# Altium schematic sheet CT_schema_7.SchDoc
size 371 x 336 mm
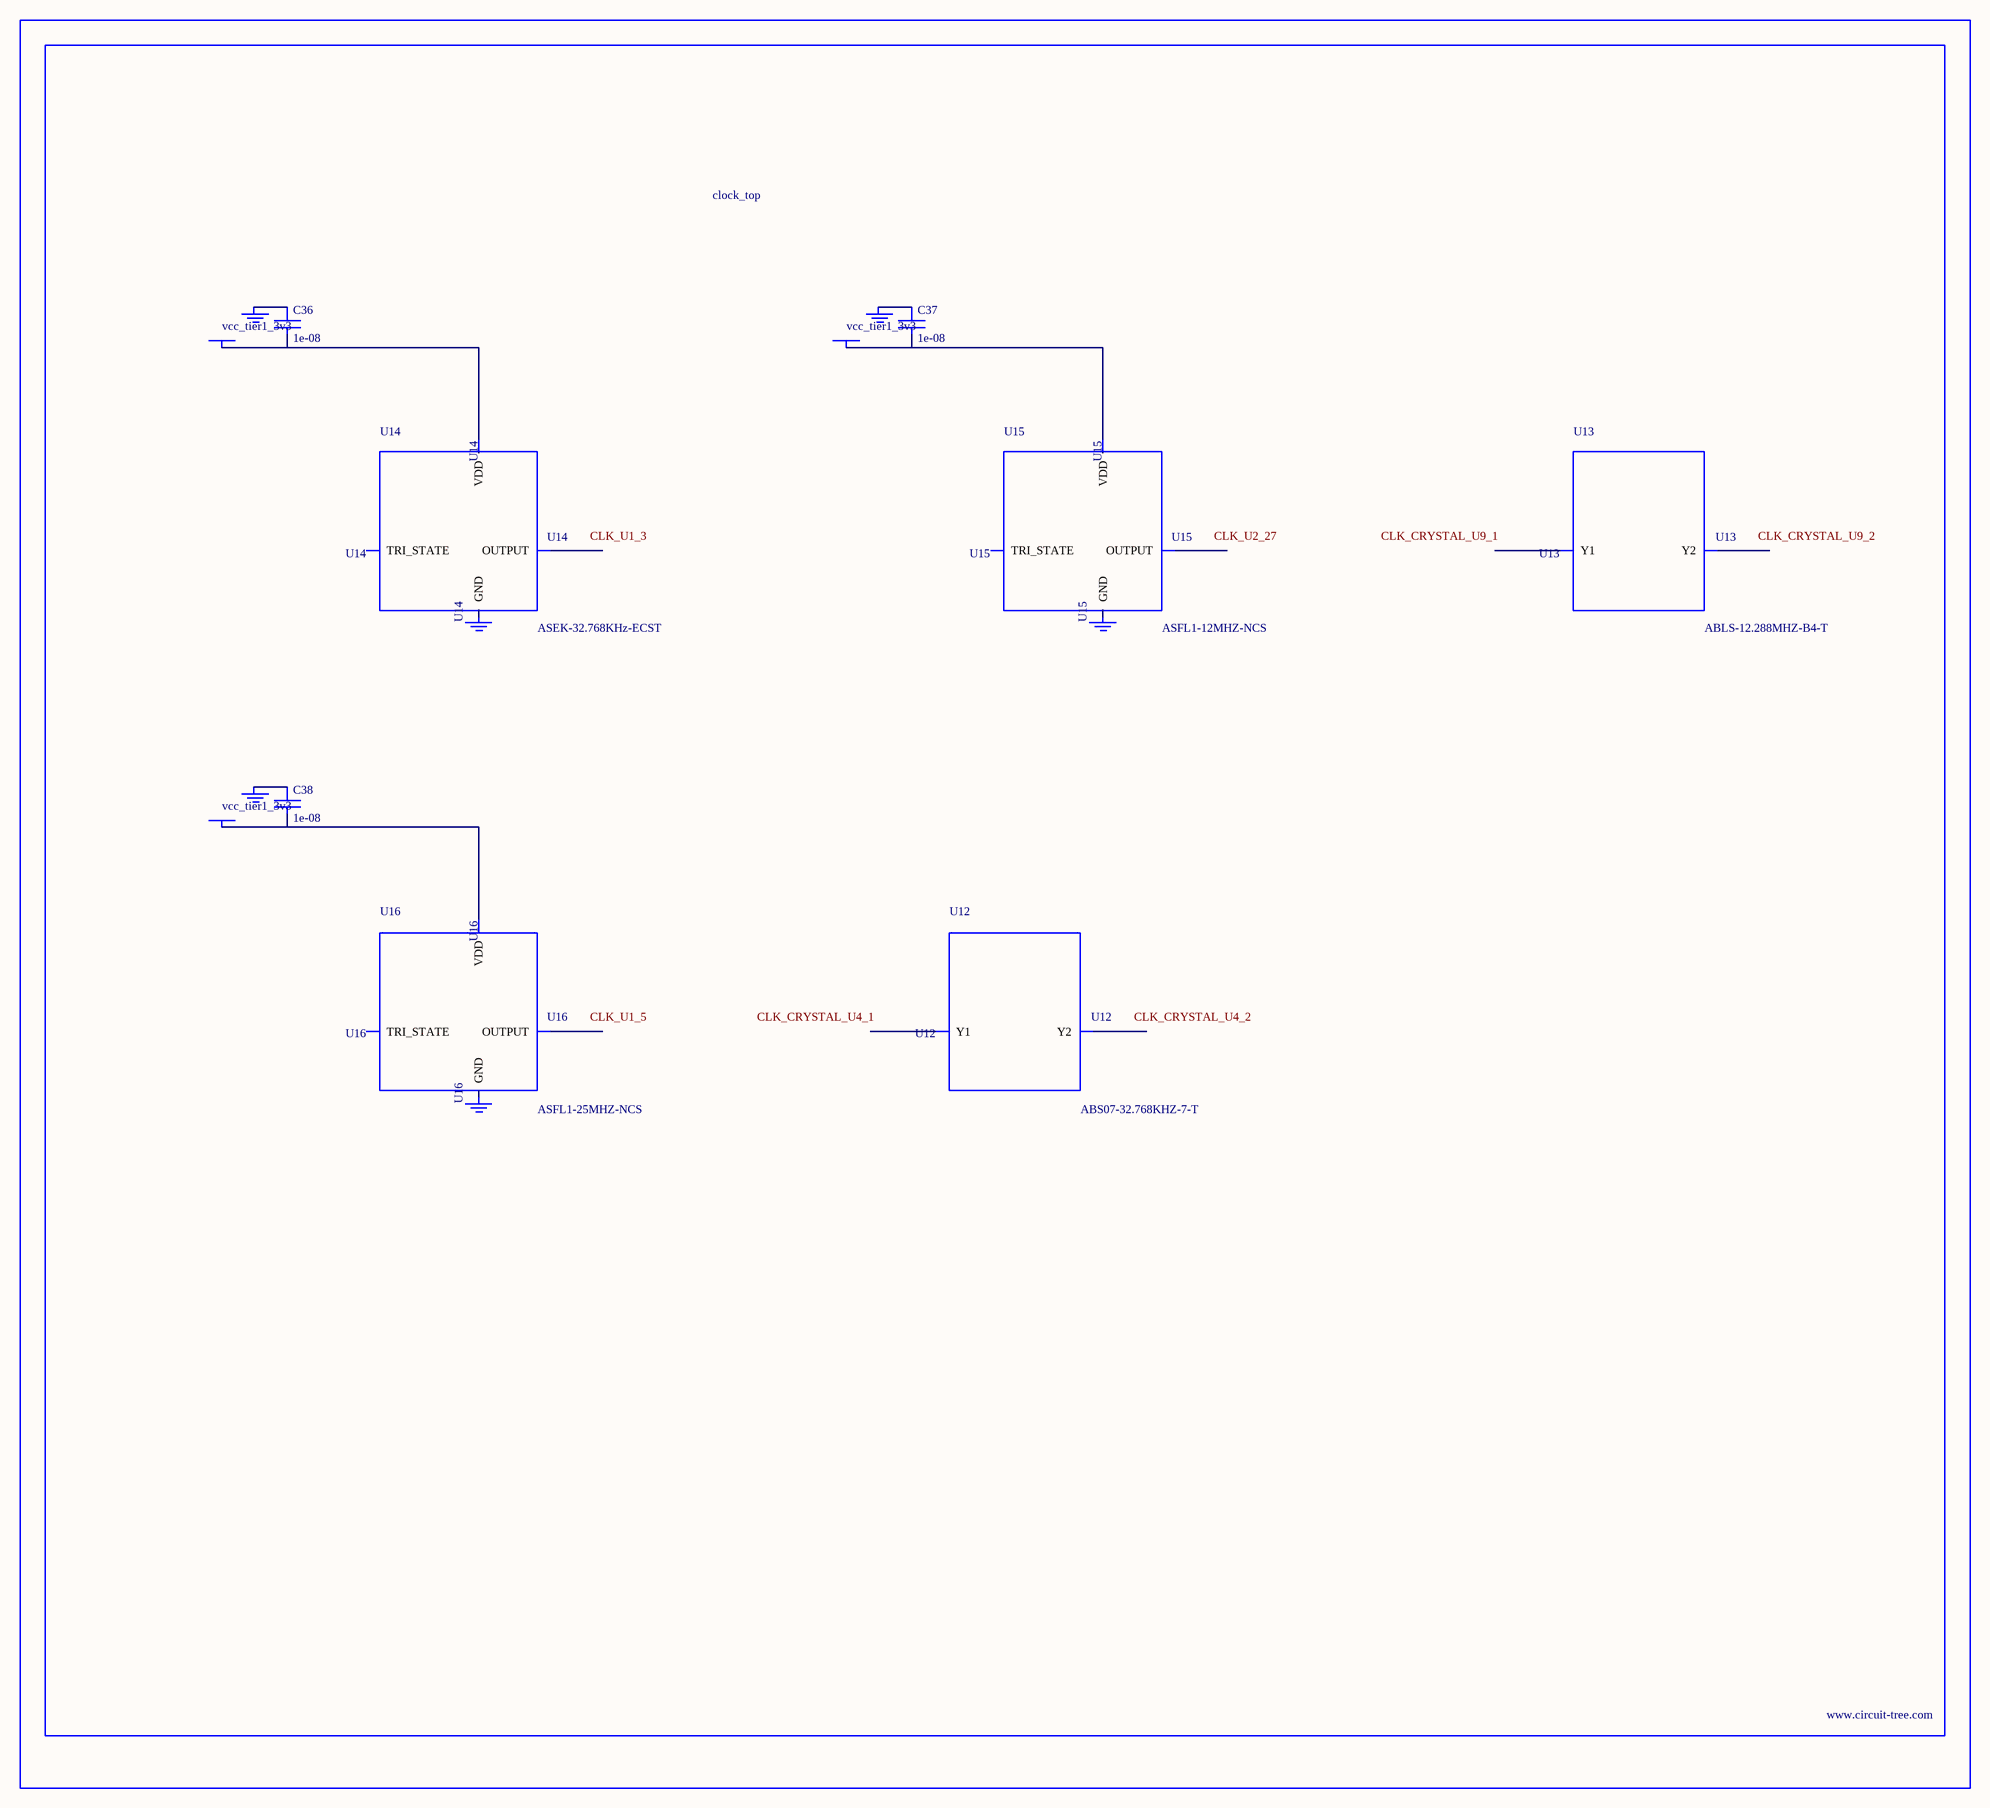
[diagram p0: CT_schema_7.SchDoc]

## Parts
BORDER6  (no value)
C36  1e-08  [C0402]
C37  1e-08  [C0402]
C38  1e-08  [C0402]
GND_INSTANCE_6_0  (no value)
GND_INSTANCE_6_1  (no value)
GND_INSTANCE_6_2  (no value)
GND_INSTANCE_6_3  (no value)
GND_INSTANCE_6_4  (no value)
GND_INSTANCE_6_5  (no value)
POWER_INSTANCE_6_0  vcc_tier1_3v3
POWER_INSTANCE_6_1  vcc_tier1_3v3
POWER_INSTANCE_6_2  vcc_tier1_3v3
U12  ABS07-32.768KHZ-7-T  [ABS07-32.768KHZ-7-T]
U13  ABLS-12.288MHZ-B4-T  [ABLS-12.288MHZ-B4-T]
U14  ASEK-32.768KHz-ECST  [ASEK]
U15  ASFL1-12MHZ-NCS  [ASFL1]
U16  ASFL1-25MHZ-NCS  [ASFL1]

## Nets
NetC36_1: C36.1 GND_INSTANCE_6_0.0(GND)
NetC36_2: C36.2 POWER_INSTANCE_6_0.0(PWR) U14.4(VDD)
NetC37_1: C37.1 GND_INSTANCE_6_2.0(GND)
NetC37_2: C37.2 POWER_INSTANCE_6_1.0(PWR) U15.4(VDD)
NetC38_1: C38.1 GND_INSTANCE_6_4.0(GND)
NetC38_2: C38.2 POWER_INSTANCE_6_2.0(PWR) U16.4(VDD)

Not connected (* = marked no-connect by the designer): GND_INSTANCE_6_1 0(GND); GND_INSTANCE_6_3 0(GND); GND_INSTANCE_6_5 0(GND); U12 1(Y1) 2(Y2); U13 1(Y1) 2(Y2); U14 1(TRI_STATE) 2(GND) 3(OUTPUT); U15 1(TRI_STATE) 2(GND) 3(OUTPUT); U16 1(TRI_STATE) 2(GND) 3(OUTPUT)

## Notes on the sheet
- Labels drawn without touching a wire or pin: CLK_CRYSTAL_U4_1, CLK_CRYSTAL_U4_2, CLK_CRYSTAL_U9_1, CLK_CRYSTAL_U9_2, CLK_U1_3, CLK_U1_5, CLK_U2_27

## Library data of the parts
BORDER6 = BORDER_PAGE6
C36-C38 = C0402C103K3RAC
GND_INSTANCE_6_0-GND_INSTANCE_6_5 = GND
POWER_INSTANCE_6_0-POWER_INSTANCE_6_2 = PWR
